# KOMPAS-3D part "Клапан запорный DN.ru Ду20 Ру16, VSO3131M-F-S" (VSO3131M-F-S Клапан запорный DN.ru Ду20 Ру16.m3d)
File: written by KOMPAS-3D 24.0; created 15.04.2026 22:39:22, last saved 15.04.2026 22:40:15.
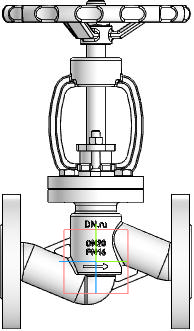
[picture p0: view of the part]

Document properties: Автор: R2D2; Полное имя файла: E:\Работа\Зайцев\VSO3131M-F-S Клапан запорный DN.ru Ду15-100 Ру16\DN20\VSO3131M-F-S Клапан запорный DN.ru Ду20 Ру16.m3d

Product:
- Part/product: Клапан запорный DN.ru Ду20 Ру16  | designation VSO3131M-F-S
    Масса: 4.05
    Раздел спецификации: Прочие изделия
    Примечание: D090-02947

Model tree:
1. Операция без истории:1

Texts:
  VSO3131M-F-S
